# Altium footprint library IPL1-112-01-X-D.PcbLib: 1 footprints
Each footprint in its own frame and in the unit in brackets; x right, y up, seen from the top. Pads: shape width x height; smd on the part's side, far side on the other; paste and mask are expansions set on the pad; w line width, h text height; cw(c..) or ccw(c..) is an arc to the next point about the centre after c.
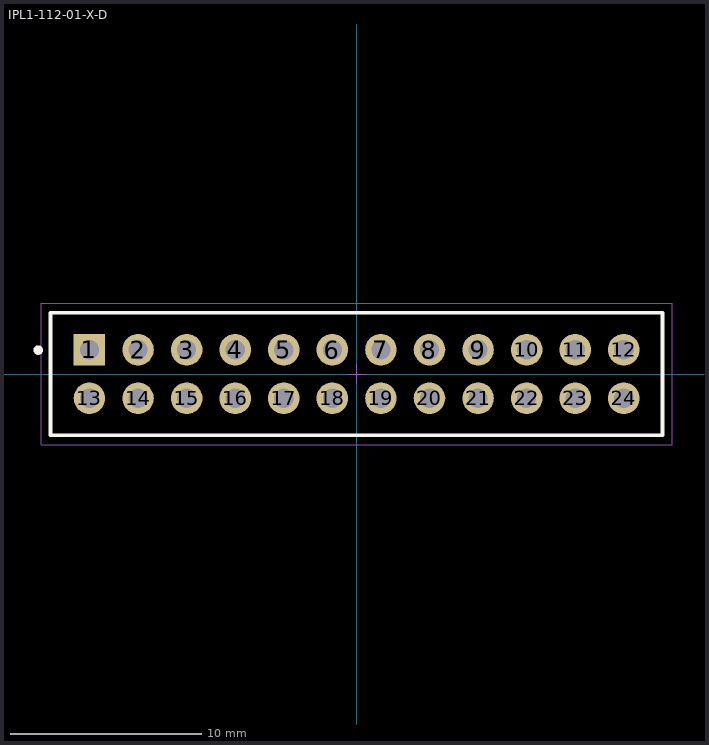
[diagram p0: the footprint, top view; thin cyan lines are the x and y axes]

## IPL1-112-01-X-D [mm] "2.54mm pitch, 24 pin, isolated power locking header"
height 8.13
pads (24):
  rect 1.65x1.65 / inner round 1.65 / far side rect 1.65x1.65 hole 1 mask+0: 1(-13.97,1.27)
  round 1.65 hole 1 mask+0: 2(-11.43,1.27) 3(-8.89,1.27) 4(-6.35,1.27) 5(-3.81,1.27) 6(-1.27,1.27) 7(1.27,1.27) 8(3.81,1.27) 9(6.35,1.27) 10(8.89,1.27) 11(11.43,1.27) 12(13.97,1.27) 13(-13.97,-1.27) 14(-11.43,-1.27) 15(-8.89,-1.27) 16(-6.35,-1.27) 17(-3.81,-1.27) 18(-1.27,-1.27) 19(1.27,-1.27) 20(3.81,-1.27) 21(6.35,-1.27) 22(8.89,-1.27) 23(11.43,-1.27) 24(13.97,-1.27)
Top Overlay:
  circle w0.25: c-16.65,1.25 r0.125
  lines w0.2: -16,-3.2 -16,3.2 16,3.2 16,-3.2 -16,-3.2
Mechanical 12:
  lines w0.001: -16,-3.2 -16,3.2 16,3.2 16,-3.2 -16,-3.2
Mechanical 13:
  lines w0.1: -16,-3.2 -16,3.2 16,3.2 16,-3.2 -16,-3.2
  text ".Designator" at 0,0 h1.52
Mechanical 15:
  lines w0.05: -0.5,0 0.5,0 ; 0,-0.5 0,0.5 ; -16.5,-3.7 -16.5,3.7 16.5,3.7 16.5,-3.7 -16.5,-3.7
